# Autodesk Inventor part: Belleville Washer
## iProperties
Author: Cory McConnell
Shininess: 64.0
Angle Display Precision: 2
Document Length Units: 11272
Document Angle Units: 11286
Document Time Units: 11279
Document Mass Units: 11290
Document Length Units Precision: 3
Document Angle Units Precision: 2
Compacted: True
PropertySet Name: _Private Model Information
Created: 2002-04
Part Number: Belleville Washer
Material: Steel, High Strength Low Alloy
Description: BELLEVILLE SPRING WSHR
Document SubType Name: Modeling
Designer: CM
Control State: 0
Master: False
Checked Out: False
PropertySet Name: Design Tracking Control
Density: 10.49
Volumn: 2.304646865681294
Area: 8.437628188859923
PropertySet Name: Model Information
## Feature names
1. Revolution3
